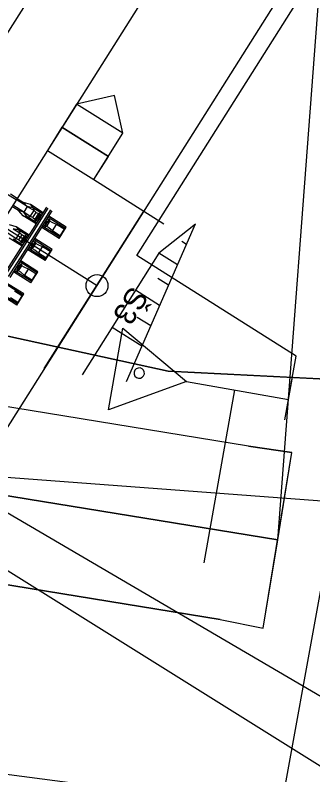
# Model space of a CAD drawing. Extents: x -746176 to -739709, y -1128407 to -1124482.
# Drawn here: x -743170.26 to -743163.48, y -1127104.77 to -1127087.46 of the extents above; entities that cross this region are included whole.
import ezdxf

# ---------------------------------------------------------------- set-up
doc = ezdxf.new("R2010")
doc.units = 0
for name, color, linetype in [('Vrstva 18', 7, 'Continuous'), ('Vrstva 22', 7, 'Continuous'), ('Vrstva 24', 7, 'Continuous'), ('Vrstva 25', 7, 'Continuous'), ('Vrstva 29', 7, 'Continuous'), ('Vrstva 3', 7, 'Continuous'), ('Vrstva 30', 7, 'Continuous'), ('Vrstva 33', 7, 'Continuous'), ('Vrstva 36', 7, 'Continuous'), ('Vrstva 37', 7, 'Continuous'), ('Vrstva 38', 7, 'Continuous'), ('Vrstva 41', 7, 'Continuous'), ('Vrstva 48', 7, 'Continuous'), ('Vrstva 5', 7, 'Continuous'), ('Vrstva 8', 7, 'Continuous')]:
    doc.layers.add(name, color=color, linetype=linetype)

msp = doc.modelspace()

# ---------------------------------------------------------------- linework, layer by layer
at = {"layer": 'Vrstva 18'}
for points in [[(-743072.487, -1126932.751), (-743098.647, -1126974.146), (-743125.94, -1127017.384), (-743152.604, -1127059.608), (-743175.023, -1127095.116), (-743199.163, -1127133.346), (-743215.971, -1127159.941), (-743232.818, -1127186.515), (-743247.456, -1127209.811), (-743254.52, -1127221.639), (-743261.299, -1127233.691), (-743264.155, -1127239.195), (-743264.862, -1127241.108), (-743267.337, -1127245.816), (-743268.289, -1127247.159), (-743271.711, -1127253.75), (-743281.122, -1127274.196), (-743291.923, -1127301.42), (-743296.724, -1127315.222), (-743301.116, -1127329.128), (-743306.787, -1127349.506)], [(-743164.036, -1127096.193), (-743163.862, -1127095.231), (-743167.492, -1127092.937), (-743158.53, -1127078.745)], [(-743168.471, -1127091.206), (-743166.88, -1127092.211)]]:
    msp.add_lwpolyline(points, dxfattribs=at)
at = {"layer": 'Vrstva 22'}
for p, q in [((-743168.004, -1127089.286), (-743168.865, -1127089.483)), ((-743167.807, -1127090.147), (-743168.004, -1127089.286)), ((-743168.865, -1127089.483), (-743169.53, -1127090.542)), ((-743167.807, -1127090.147), (-743168.865, -1127089.483)), ((-743169.198, -1127090.012), (-743168.139, -1127090.677)), ((-743168.471, -1127091.206), (-743167.807, -1127090.147)), ((-743169.53, -1127090.542), (-743168.471, -1127091.206)), ((-743168.139, -1127096.449), (-743167.81, -1127094.588)), ((-743167.81, -1127094.588), (-743166.363, -1127095.804)), ((-743166.363, -1127095.804), (-743168.139, -1127096.449)), ((-743166.363, -1127095.804), (-743164.036, -1127096.216)), ((-743164.119, -1127096.681), (-743163.954, -1127095.75)), ((-743165.267, -1127095.997), (-743165.964, -1127099.936))]:
    msp.add_line(p, q, dxfattribs=at)
msp.add_lwpolyline([(-743168.471, -1127091.206), (-743168.139, -1127090.677), (-743169.198, -1127090.012), (-743169.53, -1127090.542), (-743168.471, -1127091.206)], dxfattribs=at)
for start, end in [(79.9608, 259.9608), (259.9608, 79.9608)]:
    msp.add_arc((-743167.437, -1127095.614), 0.118, start, end, dxfattribs=at)
at = {"layer": 'Vrstva 24'}
for p, q in [((-743164.95, -1127097.281), (-743171.211, -1127096.261)), ((-743164.95, -1127097.281), (-743163.96, -1127097.421)), ((-743164.612, -1127101.425), (-743163.96, -1127097.421)), ((-743165.593, -1127101.229), (-743173.53, -1127099.936)), ((-743165.593, -1127101.229), (-743164.612, -1127101.425))]:
    msp.add_line(p, q, dxfattribs=at)
at = {"layer": 'Vrstva 25'}
msp.add_line((-743164.284, -1127099.415), (-743182.5, -1127096.45), dxfattribs=at)
at = {"layer": 'Vrstva 29'}
msp.add_lwpolyline([(-743143.427, -1127049.192), (-743169.53, -1127090.542)], dxfattribs=at)
at = {"layer": 'Vrstva 3'}
msp.add_lwpolyline([(-743184.002, -1127091.458), (-743185.918, -1127102.24), (-743183.34, -1127102.57), (-743171.62, -1127104.6), (-743164.211, -1127105.572), (-743162.439, -1127095.793), (-743166.78, -1127095.57), (-743176.42, -1127093.47), (-743180.17, -1127093.19), (-743180.08, -1127092.14)], close=True, dxfattribs=at)
at = {"layer": 'Vrstva 30'}
for p, q in [((-743160.679, -1127051.634), (-743164.286, -1127099.423)), ((-743129.509, -1127122.8), (-743175.485, -1127095.847)), ((-743148.502, -1127099.644), (-743174.29, -1127097.707)), ((-743109.419, -1127138.306), (-743174.121, -1127097.814))]:
    msp.add_line(p, q, dxfattribs=at)
at = {"layer": 'Vrstva 33'}
msp.add_lwpolyline([(-743159.64, -1127094.74), (-743160.17, -1127095.91), (-743166.78, -1127095.57), (-743176.42, -1127093.47), (-743180.17, -1127093.19), (-743180.08, -1127092.14)], dxfattribs=at)
at = {"layer": 'Vrstva 36'}
for p, q in [((-743166.364, -1127092.684), (-743166.469, -1127092.618)), ((-743166.567, -1127093.147), (-743166.987, -1127092.882)), ((-743166.77, -1127093.61), (-743167.012, -1127093.458)), ((-743166.973, -1127094.073), (-743167.521, -1127093.728)), ((-743167.176, -1127094.536), (-743167.482, -1127094.344)), ((-743167.379, -1127095), (-743168.055, -1127094.573))]:
    msp.add_line(p, q, dxfattribs=at)
for points in [[(-743167.343, -1127091.922), (-743169.607, -1127095.509)], [(-743166.158, -1127092.217), (-743166.987, -1127092.882), (-743168.735, -1127095.651)], [(-743166.161, -1127092.221), (-743167.737, -1127095.814)]]:
    msp.add_lwpolyline(points, dxfattribs=at)
at = {"layer": 'Vrstva 37'}
for points in [[(-743175.637, -1127105.086), (-743168.399, -1127093.621), (-743157.384, -1127076.172), (-743151.775, -1127072.311)], [(-743172.796, -1127090.845), (-743168.399, -1127093.621)]]:
    msp.add_lwpolyline(points, dxfattribs=at)
msp.add_circle((-743168.399, -1127093.621), 0.25, dxfattribs=at)
at = {"layer": 'Vrstva 38'}
for p, q in [((-743170.487, -1127091.505), (-743170.238, -1127091.662)), ((-743170.219, -1127091.633), (-743170.367, -1127091.539)), ((-743169.988, -1127091.82), (-743170.238, -1127091.662)), ((-743170.219, -1127091.633), (-743170.071, -1127091.726)), ((-743170.188, -1127091.912), (-743170.336, -1127091.819)), ((-743169.916, -1127091.776), (-743170.071, -1127091.726)), ((-743169.988, -1127091.82), (-743170.071, -1127091.726)), ((-743169.988, -1127091.82), (-743170.068, -1127091.947)), ((-743169.988, -1127091.82), (-743169.833, -1127091.912)), ((-743169.857, -1127091.847), (-743169.988, -1127091.82)), ((-743169.916, -1127091.776), (-743169.857, -1127091.847)), ((-743169.624, -1127091.961), (-743169.916, -1127091.776)), ((-743169.864, -1127092.342), (-743169.544, -1127091.834)), ((-743169.857, -1127091.847), (-743169.833, -1127091.912)), ((-743169.639, -1127091.986), (-743169.857, -1127091.847)), ((-743169.831, -1127092.362), (-743169.511, -1127091.855)), ((-743170.077, -1127092.03), (-743170.188, -1127091.912)), ((-743170.068, -1127091.947), (-743170.188, -1127091.912)), ((-743170.077, -1127092.03), (-743169.988, -1127092.054)), ((-743169.784, -1127092.215), (-743170.077, -1127092.03)), ((-743169.988, -1127092.054), (-743170.068, -1127091.947)), ((-743169.918, -1127092.047), (-743169.833, -1127091.912)), ((-743169.861, -1127092.072), (-743169.786, -1127091.953)), ((-743169.833, -1127091.912), (-743169.786, -1127091.953)), ((-743169.786, -1127091.953), (-743169.734, -1127091.98)), ((-743169.77, -1127092.401), (-743169.45, -1127091.894)), ((-743169.737, -1127092.422), (-743169.417, -1127091.914)), ((-743169.734, -1127091.98), (-743169.719, -1127091.976)), ((-743169.725, -1127092.043), (-743169.731, -1127092.043)), ((-743169.692, -1127092.068), (-743169.725, -1127092.043)), ((-743169.661, -1127092.02), (-743169.696, -1127091.997)), ((-743169.102, -1127092.29), (-743169.497, -1127092.041)), ((-743169.988, -1127092.054), (-743169.918, -1127092.047)), ((-743169.768, -1127092.19), (-743169.988, -1127092.054)), ((-743169.861, -1127092.072), (-743169.814, -1127092.107)), ((-743169.814, -1127092.107), (-743169.811, -1127092.123)), ((-743169.747, -1127092.156), (-743169.783, -1127092.134)), ((-743169.754, -1127092.089), (-743169.755, -1127092.081)), ((-743169.716, -1127092.106), (-743169.755, -1127092.081)), ((-743169.716, -1127092.106), (-743169.754, -1127092.089)), ((-743169.731, -1127092.043), (-743169.692, -1127092.068)), ((-743169.692, -1127092.068), (-743169.716, -1127092.106)), ((-743169.565, -1127092.149), (-743169.589, -1127092.186)), ((-743169.589, -1127092.186), (-743169.549, -1127092.211)), ((-743169.589, -1127092.186), (-743169.556, -1127092.213)), ((-743169.525, -1127092.173), (-743169.565, -1127092.149)), ((-743169.565, -1127092.149), (-743169.527, -1127092.167)), ((-743169.556, -1127092.213), (-743169.549, -1127092.211)), ((-743169.5, -1127092.124), (-743169.535, -1127092.101)), ((-743169.527, -1127092.167), (-743169.525, -1127092.173)), ((-743169.12, -1127092.318), (-743169.513, -1127092.067)), ((-743169.47, -1127092.152), (-743169.472, -1127092.135)), ((-743169.47, -1127092.152), (-743169.472, -1127092.135)), ((-743169.419, -1127092.185), (-743169.47, -1127092.153)), ((-743169.419, -1127092.185), (-743169.47, -1127092.153)), ((-743169.318, -1127092.228), (-743169.419, -1127092.185)), ((-743169.318, -1127092.228), (-743169.419, -1127092.185)), ((-743170.237, -1127092.284), (-743170.391, -1127092.234)), ((-743170.308, -1127092.327), (-743170.153, -1127092.419)), ((-743170.177, -1127092.354), (-743170.308, -1127092.327)), ((-743170.237, -1127092.284), (-743170.177, -1127092.354)), ((-743169.944, -1127092.468), (-743170.237, -1127092.284)), ((-743170.184, -1127092.849), (-743169.864, -1127092.342)), ((-743170.177, -1127092.354), (-743170.153, -1127092.419)), ((-743169.96, -1127092.493), (-743170.177, -1127092.354)), ((-743170.151, -1127092.87), (-743169.831, -1127092.362)), ((-743169.262, -1127092.544), (-743169.657, -1127092.295)), ((-743169.245, -1127092.516), (-743169.641, -1127092.269)), ((-743169.584, -1127092.257), (-743169.619, -1127092.235)), ((-743169.545, -1127092.271), (-743169.562, -1127092.277)), ((-743169.494, -1127092.304), (-743169.545, -1127092.271)), ((-743169.412, -1127092.376), (-743169.494, -1127092.304)), ((-743169.412, -1127092.376), (-743169.318, -1127092.228)), ((-743169.242, -1127092.483), (-743169.412, -1127092.376)), ((-743169.149, -1127092.335), (-743169.318, -1127092.228)), ((-743169.262, -1127092.544), (-743169.102, -1127092.29)), ((-743169.149, -1127092.335), (-743169.242, -1127092.483)), ((-743169.117, -1127092.314), (-743169.149, -1127092.335)), ((-743170.104, -1127092.722), (-743170.397, -1127092.537)), ((-743170.308, -1127092.561), (-743170.239, -1127092.555)), ((-743170.089, -1127092.697), (-743170.308, -1127092.561)), ((-743170.239, -1127092.555), (-743170.153, -1127092.419)), ((-743170.181, -1127092.579), (-743170.106, -1127092.461)), ((-743170.153, -1127092.419), (-743170.106, -1127092.461)), ((-743170.106, -1127092.461), (-743170.055, -1127092.488)), ((-743170.09, -1127092.908), (-743169.77, -1127092.401)), ((-743170.057, -1127092.929), (-743169.737, -1127092.422)), ((-743170.055, -1127092.488), (-743170.039, -1127092.484)), ((-743170.045, -1127092.55), (-743170.051, -1127092.551)), ((-743170.051, -1127092.551), (-743170.012, -1127092.576)), ((-743170.012, -1127092.576), (-743170.045, -1127092.55)), ((-743169.981, -1127092.527), (-743170.016, -1127092.504)), ((-743169.422, -1127092.798), (-743169.817, -1127092.549)), ((-743169.247, -1127092.52), (-743169.242, -1127092.483)), ((-743170.181, -1127092.579), (-743170.134, -1127092.614)), ((-743170.134, -1127092.614), (-743170.131, -1127092.63)), ((-743170.067, -1127092.664), (-743170.103, -1127092.642)), ((-743170.074, -1127092.596), (-743170.075, -1127092.589)), ((-743170.036, -1127092.614), (-743170.075, -1127092.589)), ((-743170.036, -1127092.614), (-743170.074, -1127092.596)), ((-743170.012, -1127092.576), (-743170.036, -1127092.614)), ((-743169.885, -1127092.656), (-743169.909, -1127092.694)), ((-743169.909, -1127092.694), (-743169.869, -1127092.719)), ((-743169.909, -1127092.694), (-743169.876, -1127092.721)), ((-743169.845, -1127092.681), (-743169.885, -1127092.656)), ((-743169.885, -1127092.656), (-743169.847, -1127092.675)), ((-743169.876, -1127092.721), (-743169.869, -1127092.719)), ((-743169.82, -1127092.631), (-743169.855, -1127092.608)), ((-743169.847, -1127092.675), (-743169.845, -1127092.681)), ((-743169.44, -1127092.825), (-743169.833, -1127092.574)), ((-743169.79, -1127092.66), (-743169.792, -1127092.642)), ((-743169.79, -1127092.66), (-743169.792, -1127092.642)), ((-743169.739, -1127092.692), (-743169.79, -1127092.66)), ((-743169.739, -1127092.692), (-743169.79, -1127092.66)), ((-743169.638, -1127092.735), (-743169.739, -1127092.692)), ((-743169.638, -1127092.735), (-743169.739, -1127092.692)), ((-743169.732, -1127092.883), (-743169.638, -1127092.735)), ((-743169.469, -1127092.842), (-743169.638, -1127092.735)), ((-743170.505, -1127093.356), (-743170.184, -1127092.849)), ((-743170.472, -1127093.377), (-743170.151, -1127092.87)), ((-743170.411, -1127093.415), (-743170.09, -1127092.908)), ((-743169.583, -1127093.051), (-743169.977, -1127092.802)), ((-743169.565, -1127093.023), (-743169.961, -1127092.777)), ((-743169.904, -1127092.764), (-743169.94, -1127092.742)), ((-743169.865, -1127092.779), (-743169.882, -1127092.784)), ((-743169.814, -1127092.811), (-743169.865, -1127092.779)), ((-743169.732, -1127092.883), (-743169.814, -1127092.811)), ((-743169.563, -1127092.99), (-743169.732, -1127092.883)), ((-743169.583, -1127093.051), (-743169.422, -1127092.798)), ((-743169.469, -1127092.842), (-743169.563, -1127092.99)), ((-743169.437, -1127092.821), (-743169.469, -1127092.842)), ((-743170.378, -1127093.436), (-743170.057, -1127092.929)), ((-743169.761, -1127093.333), (-743170.153, -1127093.081)), ((-743169.743, -1127093.305), (-743170.137, -1127093.056)), ((-743169.568, -1127093.028), (-743169.563, -1127092.99)), ((-743170.224, -1127093.272), (-743170.26, -1127093.25)), ((-743170.205, -1127093.163), (-743170.229, -1127093.201)), ((-743170.229, -1127093.201), (-743170.19, -1127093.226)), ((-743170.229, -1127093.201), (-743170.197, -1127093.228)), ((-743170.166, -1127093.188), (-743170.205, -1127093.163)), ((-743170.205, -1127093.163), (-743170.168, -1127093.182)), ((-743170.197, -1127093.228), (-743170.19, -1127093.226)), ((-743170.14, -1127093.138), (-743170.175, -1127093.116)), ((-743170.168, -1127093.182), (-743170.166, -1127093.188)), ((-743170.11, -1127093.167), (-743170.113, -1127093.15)), ((-743170.11, -1127093.167), (-743170.113, -1127093.15)), ((-743170.059, -1127093.2), (-743170.111, -1127093.167)), ((-743170.059, -1127093.2), (-743170.111, -1127093.167)), ((-743169.959, -1127093.243), (-743170.059, -1127093.2)), ((-743169.959, -1127093.243), (-743170.059, -1127093.2)), ((-743170.052, -1127093.391), (-743169.959, -1127093.243)), ((-743169.79, -1127093.349), (-743169.959, -1127093.243)), ((-743169.903, -1127093.559), (-743170.298, -1127093.31)), ((-743169.885, -1127093.531), (-743170.281, -1127093.284)), ((-743170.186, -1127093.286), (-743170.202, -1127093.292)), ((-743170.134, -1127093.318), (-743170.186, -1127093.286)), ((-743170.052, -1127093.391), (-743170.134, -1127093.318)), ((-743169.883, -1127093.497), (-743170.052, -1127093.391)), ((-743169.903, -1127093.559), (-743169.743, -1127093.305)), ((-743169.79, -1127093.349), (-743169.883, -1127093.497)), ((-743169.758, -1127093.329), (-743169.79, -1127093.349)), ((-743170.081, -1127093.84), (-743170.474, -1127093.589)), ((-743170.063, -1127093.812), (-743170.458, -1127093.563)), ((-743169.888, -1127093.535), (-743169.883, -1127093.497)), ((-743170.11, -1127093.857), (-743170.279, -1127093.75)), ((-743170.223, -1127094.066), (-743170.618, -1127093.817)), ((-743170.206, -1127094.038), (-743170.602, -1127093.791)), ((-743170.203, -1127094.005), (-743170.372, -1127093.898)), ((-743170.223, -1127094.066), (-743170.063, -1127093.812)), ((-743170.11, -1127093.857), (-743170.203, -1127094.005)), ((-743170.078, -1127093.836), (-743170.11, -1127093.857)), ((-743170.208, -1127094.042), (-743170.203, -1127094.005))]:
    msp.add_line(p, q, dxfattribs=at)
for points in [[(-743169.861, -1127092.072), (-743169.918, -1127092.047), (-743170.068, -1127091.947), (-743170.318, -1127091.789)], [(-743169.734, -1127091.98), (-743169.814, -1127092.107)], [(-743169.788, -1127092.133), (-743169.699, -1127091.993)], [(-743169.696, -1127091.997), (-743169.725, -1127092.043)], [(-743169.696, -1127091.997), (-743169.699, -1127091.993)], [(-743169.783, -1127092.134), (-743169.788, -1127092.133)], [(-743169.754, -1127092.089), (-743169.783, -1127092.134)], [(-743169.584, -1127092.257), (-743169.556, -1127092.213)], [(-743169.495, -1127092.125), (-743169.58, -1127092.261)], [(-743169.545, -1127092.271), (-743169.47, -1127092.152)], [(-743169.527, -1127092.167), (-743169.5, -1127092.124)], [(-743169.5, -1127092.124), (-743169.495, -1127092.125)], [(-743169.5, -1127092.124), (-743169.495, -1127092.125)], [(-743170.181, -1127092.579), (-743170.239, -1127092.555), (-743170.388, -1127092.454), (-743170.638, -1127092.297)], [(-743169.584, -1127092.257), (-743169.58, -1127092.261)], [(-743170.055, -1127092.488), (-743170.134, -1127092.614)], [(-743170.108, -1127092.64), (-743170.019, -1127092.5)], [(-743170.016, -1127092.504), (-743170.045, -1127092.55)], [(-743170.016, -1127092.504), (-743170.019, -1127092.5)], [(-743170.103, -1127092.642), (-743170.108, -1127092.64)], [(-743170.074, -1127092.596), (-743170.103, -1127092.642)], [(-743169.904, -1127092.764), (-743169.877, -1127092.721)], [(-743169.815, -1127092.632), (-743169.901, -1127092.768)], [(-743169.865, -1127092.779), (-743169.79, -1127092.66)], [(-743169.847, -1127092.675), (-743169.82, -1127092.631)], [(-743169.82, -1127092.631), (-743169.815, -1127092.632)], [(-743169.82, -1127092.631), (-743169.815, -1127092.632)], [(-743169.904, -1127092.764), (-743169.901, -1127092.768)], [(-743170.224, -1127093.272), (-743170.197, -1127093.228)], [(-743170.135, -1127093.14), (-743170.221, -1127093.275)], [(-743170.186, -1127093.286), (-743170.11, -1127093.167)], [(-743170.168, -1127093.182), (-743170.14, -1127093.138)], [(-743170.14, -1127093.138), (-743170.135, -1127093.14)], [(-743170.14, -1127093.138), (-743170.135, -1127093.14)], [(-743170.224, -1127093.272), (-743170.221, -1127093.275)]]:
    msp.add_lwpolyline(points, dxfattribs=at)
for centre, radius in [((-743169.726, -1127092.074), 0.0195), ((-743169.726, -1127092.074), 0.0155), ((-743169.726, -1127092.074), 0.0115), ((-743169.555, -1127092.182), 0.0195), ((-743169.555, -1127092.182), 0.0155), ((-743169.555, -1127092.182), 0.0115), ((-743170.046, -1127092.581), 0.0195), ((-743170.046, -1127092.581), 0.0155), ((-743170.046, -1127092.581), 0.0115), ((-743169.875, -1127092.689), 0.0195), ((-743169.875, -1127092.689), 0.0155), ((-743169.875, -1127092.689), 0.0115), ((-743170.195, -1127093.196), 0.0195), ((-743170.195, -1127093.196), 0.0155), ((-743170.195, -1127093.196), 0.0115)]:
    msp.add_circle(centre, radius, dxfattribs=at)
for centre, radius, start, end in [((-743169.713, -1127091.99), 0.0143, 346.7248, 112.2532), ((-743169.797, -1127092.122), 0.0143, 183.2195, 308.7478), ((-743169.486, -1127092.136), 0.0137, 2.1748, 130.3968), ((-743169.486, -1127092.136), 0.0137, 2.1748, 130.3968), ((-743169.567, -1127092.264), 0.0137, 165.0758, 293.2978), ((-743170.033, -1127092.497), 0.0143, 346.7248, 112.2532), ((-743170.117, -1127092.629), 0.0143, 183.2195, 308.7478), ((-743169.806, -1127092.643), 0.0137, 2.1748, 130.3968), ((-743169.806, -1127092.643), 0.0137, 2.1748, 130.3968), ((-743169.887, -1127092.772), 0.0137, 165.0758, 293.2978), ((-743170.126, -1127093.15), 0.0137, 2.1748, 130.3968), ((-743170.126, -1127093.15), 0.0137, 2.1748, 130.3968), ((-743170.208, -1127093.279), 0.0137, 165.0758, 293.2978)]:
    msp.add_arc(centre, radius, start, end, dxfattribs=at)
at = {"layer": 'Vrstva 41'}
msp.add_lwpolyline([(-743169.53, -1127090.542), (-743178.712, -1127105.086)], dxfattribs=at)
at = {"layer": 'Vrstva 48'}
for p, q in [((-743164.95, -1127097.281), (-743171.211, -1127096.261)), ((-743163.96, -1127097.421), (-743164.95, -1127097.281)), ((-743164.284, -1127099.415), (-743163.96, -1127097.421)), ((-743172.37, -1127098.099), (-743164.284, -1127099.415)), ((-743164.284, -1127099.415), (-743172.37, -1127098.099)), ((-743164.612, -1127101.425), (-743164.284, -1127099.415)), ((-743173.53, -1127099.936), (-743165.593, -1127101.229)), ((-743165.593, -1127101.229), (-743164.612, -1127101.425))]:
    msp.add_line(p, q, dxfattribs=at)
at = {"layer": 'Vrstva 5'}
msp.add_lwpolyline([(-743094.82, -1126957.905), (-743108.67, -1126985.4), (-743116.735, -1126998.84), (-743124.8, -1127012.28), (-743150.075, -1127051.72), (-743175.35, -1127091.16), (-743176.93, -1127091.485), (-743178.51, -1127091.81), (-743180.08, -1127092.14), (-743180.17, -1127093.19), (-743178.295, -1127093.33), (-743176.42, -1127093.47), (-743166.78, -1127095.57), (-743163.475, -1127095.74), (-743160.17, -1127095.91), (-743159.64, -1127094.74), (-743153.71, -1127081.77), (-743147.78, -1127068.8), (-743136.47, -1127047.12), (-743114.785, -1127013.02), (-743087.685, -1126970.495), (-743082.27, -1126962.07), (-743073.035, -1126947.525)], dxfattribs=at)
at = {"layer": 'Vrstva 8'}
msp.add_lwpolyline([(-743162.439, -1127095.793), (-743160.17, -1127095.91), (-743159.64, -1127094.74), (-743153.521, -1127095.535), (-743155.344, -1127106.734), (-743164.211, -1127105.572)], close=True, dxfattribs=at)

# ---------------------------------------------------------------- texts
at = {"layer": 'Vrstva 37'}
msp.add_text('Š3', height=0.5, rotation=238, dxfattribs=at).set_placement((-743167.625, -1127093.603))

doc.saveas('drawing.dxf')
